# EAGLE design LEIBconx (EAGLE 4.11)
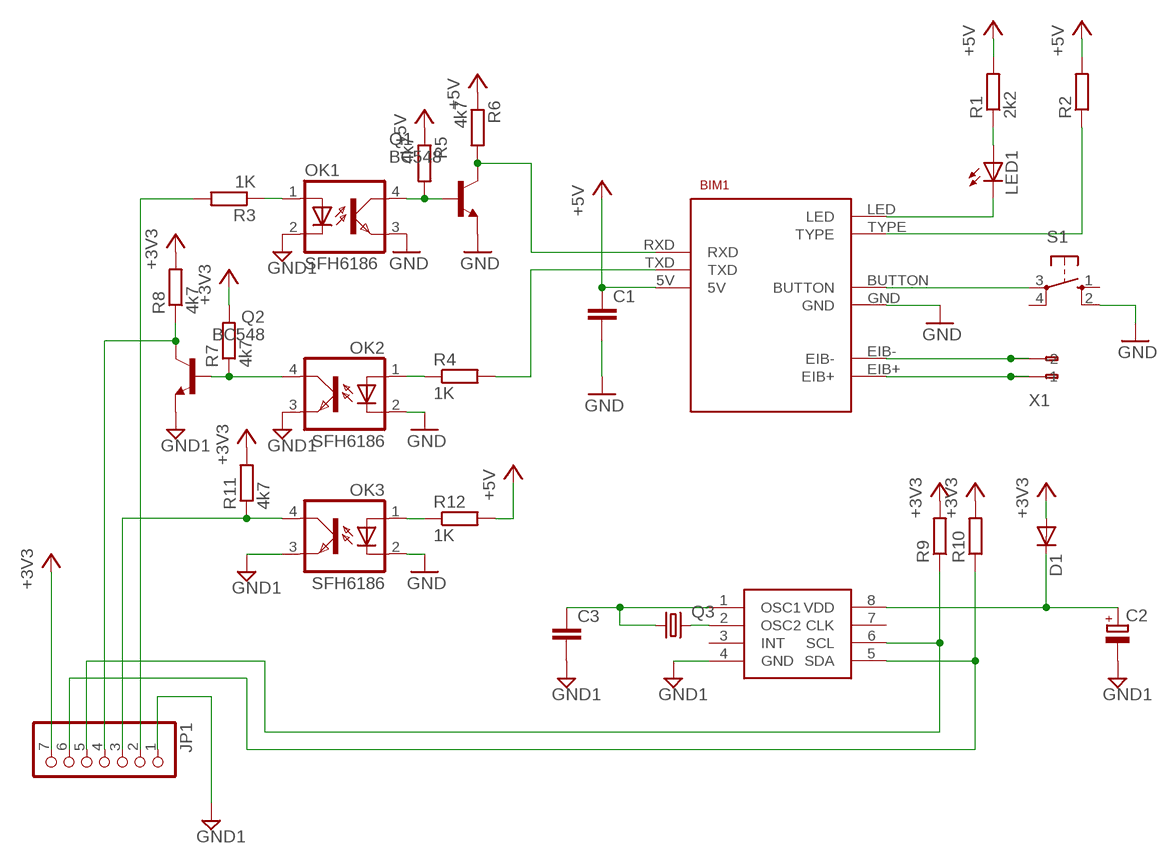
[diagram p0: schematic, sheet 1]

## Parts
BIM1  EIB-BIM-FT12  [EIB-BIM-SERIAL]
C1  C-EU050-024X044  [C050-024X044]
C2  CPOL-EUE5-13  [E5-13]
C3  C-EUC1608  [C1608]
D1  DIODE-D-5  [D-5]
JP1  PINHD-1X7  [1X07]
LED1  LED3MM  [LED3MM]
OK1  SFH6186  [SFH6186]
OK2  SFH6186  [SFH6186]
OK3  SFH6186  [SFH6186]
Q1  BC548  [TO92-EBC]
Q2  BC548  [TO92-EBC]
Q3  CRYTALTC26H  [TC26H]
R1  2k2  R-EU_0204/2V  [0204V]
R2  R-EU_0204/2V  [0204V]
R3  1K  R-EU_0207/10  [0207/10]
R4  1K  R-EU_0207/10  [0207/10]
R5  4k7  R-EU_0207/10  [0207/10]
R6  4k7  R-EU_0207/10  [0207/10]
R7  4k7  R-EU_0207/10  [0207/10]
R8  4k7  R-EU_0207/10  [0207/10]
R9  R-EU_0204/2V  [0204V]
R10  R-EU_0204/2V  [0204V]
R11  4k7  R-EU_0207/10  [0207/10]
R12  1K  R-EU_0207/10  [0207/10]
S1  10-XX  [B3F-10XX]
U$4  PCF8563  [SMD8]
X1  233-102  [233-102]

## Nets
+3V3: D1.A JP1.7 R7.2 R8.2 R9.2 R10.2 R11.2
+5V: BIM1.5V C1.1 R1.2 R2.2 R5.1 R6.1 R12.2
EIB+: BIM1.EIB+ X1.A1(-1) X1.B1(B-1)
EIB-: BIM1.EIB- X1.A2(-2) X1.B2(B-2)
GND: BIM1.GND C1.2 OK1.3(EMIT) OK2.2(C) OK3.2(C) Q1.E S1.2(S1)
GND1: C2.- C3.2 JP1.1 OK1.2(C) OK2.3(EMIT) OK3.3(EMIT) Q2.E U$4.4(GND)
N$1: LED1.A R1.1
N$3: BIM1.LED LED1.K(C)
N$4: BIM1.BUTTON S1.3(P)
N$5: BIM1.TYPE R2.1
N$6: OK2.4(COL) Q2.B R7.1
N$7: C2.+ D1.C U$4.8(VDD)
N$8: OK2.1(A) R4.1
N$9: OK1.4(COL) Q1.B R5.2
N$10: BIM1.RXD Q1.C R6.2
N$11: OK1.1(A) R3.1
N$12: OK3.1(A) R12.1
N$13: BIM1.TXD R4.2
N$14: C3.1 Q3.1 U$4.1(OSC1)
N$21: Q3.2 U$4.2(OSC2)
N$23: JP1.3 OK3.4(COL) R11.1
RXD: JP1.4 Q2.C R8.1
SCL: JP1.5 R9.1 U$4.6(SCL)
SDA: JP1.6 R10.1 U$4.5(SDA)
TXD: JP1.2 R3.2
Unconnected: S1.1(S) S1.4(P1) U$4.3(INT) U$4.7(CLK)

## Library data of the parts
BIM1 = ~EIBdevices:EIB-BIM-FT12: EIB-BIM113 mit reduzierten Pins für FT1.2 Protokoll
C1 C3 = rcl:C-EU: CAPACITOR, European symbol
C2 = rcl:CPOL-EU: POLARIZED CAPACITOR, European symbol
D1 = diode:DIODE-: DIODE
JP1 = pinhead:PINHD-1X7: PIN HEADER
LED1 = led:LED: LED
OK1-OK3 = ~EIBdevices:SFH6186: SIEMENS OPTO COUPLER
Q1 Q2 = transistor-npn:BC548*: NPN Transistor
Q3 = crystal:CRYTAL: CRYSTAL
R1-R12 = rcl:R-EU_: RESISTOR, European symbol
S1 = switch-omron:10-XX: OMRON SWITCH
U$4 = ~EIBdevices:PCF8563: PCF8563 Philips RTC (I²C)
X1 = con-wago:233-102: WAGO Cage Clamp

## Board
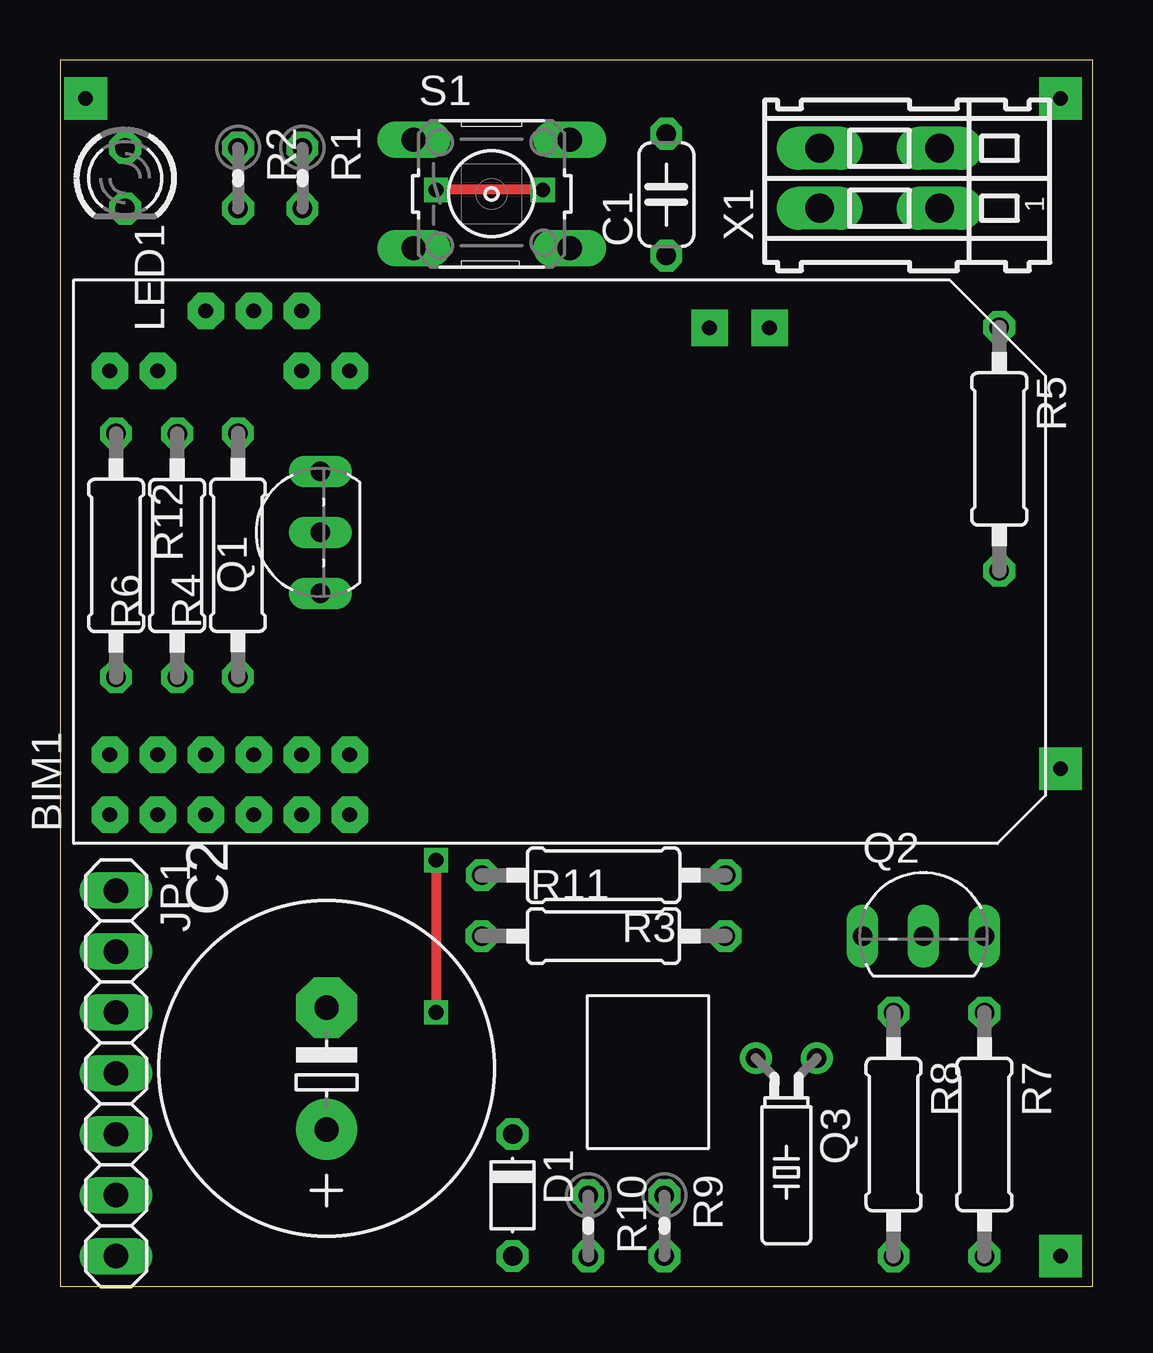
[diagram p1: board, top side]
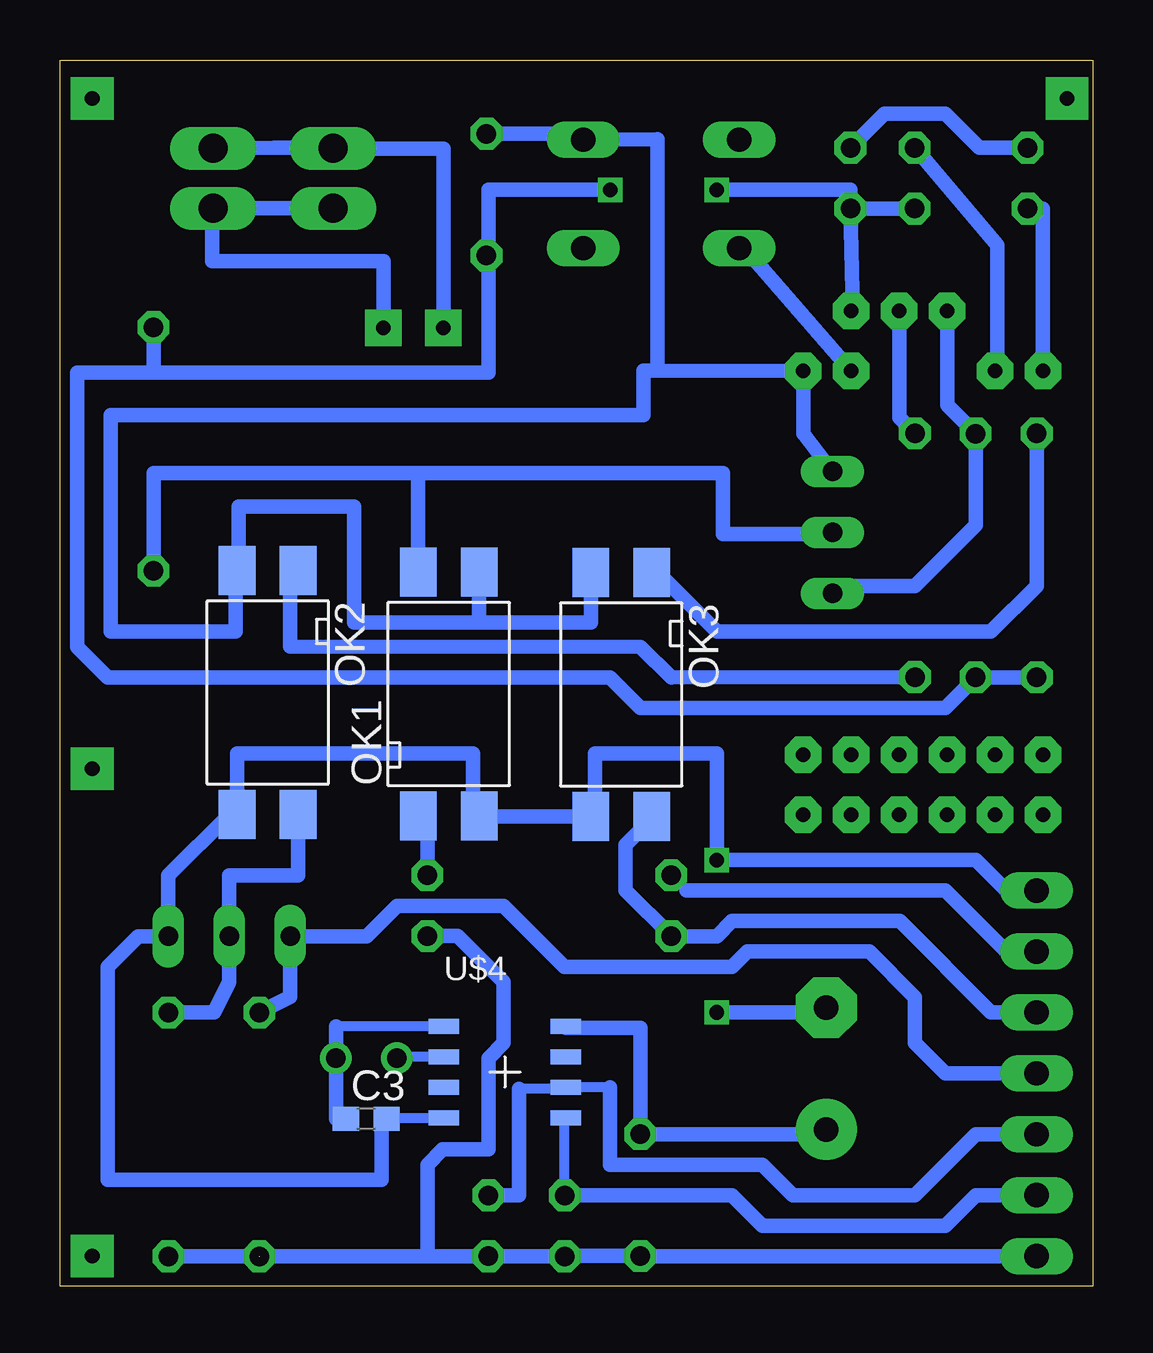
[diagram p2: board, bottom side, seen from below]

Size 43.06 x 51.12 mm. Coordinates in mm from the lower left corner, seen from the top.
Outline: 0,0 43.05,0 43.05,51.12 0,51.12 0,0
Copper layers (1*16): Top 0.035mm / dielectric 1.5mm / Bottom 0.035mm
Design rules "default": minimum track width 10mil, minimum drill 24mil, track to track 8mil, track to pad 8mil, pad to pad 8mil, via to via 8mil, smd to smd 8mil, copper to edge 40mil, drill to drill 8mil, minimum pad ring 10mil, minimum via ring 8mil, stop-mask expansion 4mil, vias tented up to drill 0mil, thermal gap 10mil

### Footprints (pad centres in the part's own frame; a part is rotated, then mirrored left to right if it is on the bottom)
EIB-BIM-SERIAL = drill 0.61 pad 1.524 octagon: 5V 22.2,31; BUTTON 19.7,31; C35V 1.2,31; GND 19.7,29; LED 19.7,39; PA0 3.7,37; PA1 1.2,39; PA2 3.7,35; PA3 1.2,37; PA4 3.7,33; PA5 1.2,35; PA6 3.7,31; PA7 1.2,33; PC7 3.7,39; PLMA 3.7,29; RESET 1.2,29; RXD 22.2,35; TXD 22.2,33; TYPE 19.7,37 | drill 0.61 pad 1.524 square: EIB+ 21.5,11.5; EIB- 21.5,14
C050-024X044 = drill 0.813 octagon: 1 -2.54,0; 2 2.54,0
E5-13 = drill 1.016 pad 2.54 round: + -2.54,0 | drill 1.016 pad 2.54 octagon: - 2.54,0
C1608 = smd 1.1 x 1: 1 -0.85,0; 2 0.85,0
D-5 = drill 0.813 octagon: A 2.54,0; C -2.54,0
1X07 = drill 1.016 long: 1 -7.62,0; 2 -5.08,0; 3 -2.54,0; 4 0,0; 5 2.54,0; 6 5.08,0; 7 7.62,0
LED3MM = drill 0.813 octagon: A -1.27,0; K 1.27,0
SFH6186 = smd 2.032 x 1.524: 1 0,2.54; 2 0,0; 3 10.16,0; 4 10.16,2.54
TO92-EBC = drill 0.813 long: B 0,-1.27; C -2.54,-1.27; E 2.54,-1.27
TC26H = drill 0.813 round: 1 -1.27,0; 2 1.27,0
0204V = drill 0.813 octagon: 1 -1.27,0; 2 1.27,0
0207/10 = drill 0.813 octagon: 1 -5.08,0; 2 5.08,0
B3F-10XX = drill 1.016 long: 1 -3.251,2.261; 2 3.251,2.261; 3 -3.251,-2.261; 4 3.251,-2.261
SMD8 = smd 0.635 x 1.27: 1 0,0; 2 1.27,0; 3 2.54,0; 4 3.81,0; 5 3.81,5.08; 6 2.54,5.08; 7 1.27,5.08; 8 0,5.08
233-102 = drill 1.2 long: A1 -1.25,2.5; A2 1.25,2.5; B1 -1.25,-2.5; B2 1.25,-2.5

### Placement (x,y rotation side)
BIM1  41.07,18.45 90 top
C1  25.28,45.5 90 top
C2  11.11,9.08 90 top
C3  30.29,6.98 0 bottom
D1  18.87,3.8 270 top
JP1  2.34,8.88 270 top
LED1  2.72,46.19 270 top
OK1  25.58,19.61 90 bottom
OK2  35.67,29.83 270 bottom
OK3  20.93,29.75 270 bottom
Q1  9.59,31.42 90 top
Q2  35.99,15.86 0 top
Q3  30.28,9.51 180 top
R1  10.1,46.19 270 top
R2  7.42,46.19 270 top
R3  22.66,17.13 180 top
R4  7.42,30.48 90 top
R5  39.15,34.9 270 top
R6  4.89,30.46 90 top
R7  38.53,6.33 270 top
R8  34.75,6.33 270 top
R9  25.2,2.52 270 top
R10  22.02,2.52 270 top
R11  22.66,14.6 0 top
R12  2.34,30.47 270 top
S1  17.99,45.53 0 top
U$4  27.05,10.84 270 bottom
X1  34.17,46.19 90 top

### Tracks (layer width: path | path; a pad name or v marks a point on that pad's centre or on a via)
+3V3  (1 unrouted)
  Bottom 0.406: 18.85,1.26 D1.A | R10.2 | R9.2 | R9.2 | R9.2 | R7.2 | R7.2
  Bottom 0.61: JP1.7 18.85,1.26 | D1.A R10.2 | R10.2 R9.2 | R9.2 27.74,1.25 | 27.74,1.25 34.72,1.25 | R11.2 26.48,14.6 24.57,12.69 24.57,10.15 25.2,9.51 25.2,5.7 27.11,5.7 27.74,5.07 27.74,1.25 | R8.2 R7.2
+5V  (via drill 0.61)
  Top 0.406: v20.12,45.71 v15.68,45.71
  Bottom 0.406: 10.01,40.6 BIM1.5V | 25.2,43.17 25.28,43.17 C1.1 | R6.1 | R6.1 | 4.88,25.39 R6.1
  Bottom 0.61: R2.2 8.06,44.92 R1.2 | R1.2 10.01,40.6 | 39.15,38.09 R5.1 | 39.15,38.09 25.2,38.09 25.2,43.17 25.2,45.71 v20.12,45.71 | R1.2 10.11,45.71 v15.68,45.71 | R6.1 6.15,24.12 18.85,24.12 20.12,25.39 41.07,25.39 42.34,26.66 42.34,38.09 39.15,38.09 | R12.2 4.88,25.39
EIB+
  Bottom 0.406: 36.71,44.94 X1.B1 36.22,44.94 36.22,45.07
  Bottom 0.61: BIM1.EIB+ 29.57,42.73 36.71,42.73 36.71,44.94 | 36.22,44.94 X1.A1
EIB-
  Bottom 0.406: 34.13,47.46 34.34,47.46 | 31.67,47.41 X1.A2
  Bottom 0.61: X1.B2 34.13,47.46 33.19,47.46 X1.A2 | BIM1.EIB- 27.07,47.41 31.67,47.41
GND
  Bottom 0.406: C1.2 24.72,48.02 | 21.16,47.79 | S1.2 21.16,47.79 | 21.16,47.79 21.16,48.04 | OK1.3 25.58,29.83 25.45,29.83 | 35.67,30.08 35.74,30.08 | 35.67,29.96 35.67,30.08 | 35.67,29.96 OK2.2 | 35.67,30.08 35.61,30.08 | 35.74,29.96 35.67,29.96
  Bottom 0.61: Q1.E 12.07,35.55 BIM1.GND 18.14,38.16 | S1.2 18.14,47.81 18.14,38.16 | 21.16,48.04 C1.2 | 18.14,38.16 18.72,38.16 18.72,36.31 40.95,36.31 40.95,27.29 35.74,27.29 35.74,29.96 | OK3.2 20.93,27.67 25.58,27.67 | 25.58,27.67 OK1.3 | 25.58,27.67 30.79,27.67 30.79,32.5 35.61,32.5 35.61,30.08
GND1  (via drill 0.61)
  Top 0.406: v15.68,17.77 v15.68,11.42
  Bottom 0.406: OK2.3 35.99,19.67 | 29.01,6.98 29.01,6.97 | 29.01,6.98 C3.2 29.64,6.78 | U$4.4 29.01,7.03 29.01,6.98 | OK1.2 25.84,19.61 25.84,19.59 | 20.75,19.67 20.84,19.59 OK3.3 | 11.31,11.42 C2.-
  Bottom 0.61: 35.99,19.67 38.53,17.13 Q2.E 39.8,14.59 41.07,13.32 41.07,4.43 29.64,4.43 29.64,6.78 | OK3.3 25.84,19.59 | OK2.3 35.67,22.21 25.84,22.21 25.84,19.61 | JP1.1 3.61,16.5 4.88,17.77 v15.68,17.77 15.68,22.21 20.75,22.21 20.75,19.67 | v15.68,11.42 11.31,11.42
N$1
  Bottom 0.406: R1.1
  Bottom 0.61: LED1.A 4.73,47.46 6.15,48.88 8.69,48.88 R1.1
N$3
  Bottom 0.406: 2.09,44.92 LED1.K | BIM1.LED 2.09,38.15
  Bottom 0.61: 2.09,38.15 2.09,44.92
N$4
  Bottom 0.406: 14.51,43.24 S1.3
  Bottom 0.61: BIM1.BUTTON 14.51,43.24
N$5
  Bottom 0.406: 3.99,38.06 3.99,38.07 BIM1.TYPE
  Bottom 0.61: R2.1 3.99,43.4 3.99,38.07
N$6
  Bottom 0.406: 37.9,11.42 R7.1
  Bottom 0.61: OK2.4 33.13,17.13 35.99,17.13 Q2.B 35.99,12.69 36.63,11.42 37.9,11.42
N$7
  Bottom 0.406: C2.+ 11.23,6.54 11.23,6.34 | 22.03,10.78 21.97,10.78 U$4.8
  Bottom 0.61: 11.23,6.34 D1.C 18.87,10.78 21.97,10.78
N$8
  Bottom 0.406: 33.45,29.83 OK2.1
  Bottom 0.61: R4.1 17.57,25.39 18.85,26.66 33.45,26.67 33.45,29.83
N$9
  Bottom 0.406: OK1.4 28.12,29.7 28.25,29.7 | Q1.B 10.86,31.35
  Bottom 0.61: R5.2 39.15,33.89 28.12,33.89 | 28.12,33.89 OK1.4 | 28.12,33.89 15.42,33.89 15.42,31.35 10.86,31.35
N$10
  Bottom 0.406: R6.2 | 10.6,29.2 10.6,29.14 Q1.C
  Bottom 0.61: BIM1.RXD 6.08,36.74 R6.2 | R6.2 4.89,31.73 7.42,29.2 10.6,29.2
N$11
  Bottom 0.406: OK1.1 27.8,19.61 27.74,19.67
  Bottom 0.61: R3.1 27.74,19.67
N$12
  Bottom 0.406: R12.1 | 18.21,29.83 18.31,29.83 OK3.1
  Bottom 0.61: R12.1 2.34,29.2 4.25,27.29 15.68,27.29 18.21,29.83
N$13
  Bottom 0.406: R4.2
  Bottom 0.61: BIM1.TXD 8.08,36.2 R4.2
N$14
  Bottom 0.406: U$4.1 31.55,10.84 | 31.55,6.98 C3.1
  Bottom 0.61: 31.55,10.84 Q3.1 31.55,6.98
N$17  (via drill 0.61 pad 1.78)
  other vias: 1.07,49.52
N$18  (via drill 0.61 pad 1.78)
  other vias: 41.71,49.52
N$19  (via drill 0.61 pad 1.78)
  other vias: 41.71,21.58
N$21
  Bottom 0.406: U$4.2 29.01,9.57 Q3.2
N$22  (via drill 0.61 pad 1.78)
  other vias: 41.71,1.26
N$23
  Bottom 0.406: 19.47,16.5 19.48,16.5 | 18.21,19.67 18.3,19.59 OK3.4 | R11.1
  Bottom 0.61: R11.1 19.47,16.5 | 19.48,16.5 19.48,18.4 18.3,19.59 | JP1.3 4.25,11.42 8.06,15.23 15.04,15.23 15.68,14.59 R11.1
RXD
  Bottom 0.61: R8.1 33.45,12.07 Q2.C 30.28,14.59 29.01,15.86 24.57,15.86 22.03,13.32 15.04,13.32 14.41,13.96 9.33,13.96 7.42,12.05 7.42,10.15 6.15,8.88 JP1.4
SCL
  Bottom 0.406: 23.93,8.24 22.03,8.24 22.03,8.3 U$4.6 20.12,8.3
  Bottom 0.61: R9.1 23.93,3.79 23.93,8.24 | 20.12,8.3 20.12,5.07 13.77,5.07 12.5,3.8 7.42,3.8 4.88,6.34 JP1.5
SDA
  Bottom 0.406: U$4.5 22.03,7.03 R10.1 | 15.04,3.8 15.04,3.79
  Bottom 0.61: 15.04,3.79 R10.1 | 15.04,3.8 13.77,2.53 6.15,2.53 4.88,3.8 JP1.6
TXD
  Bottom 0.406: R3.2 16.95,16.5
  Bottom 0.61: JP1.2 3.61,13.96 6.15,16.5 16.95,16.5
